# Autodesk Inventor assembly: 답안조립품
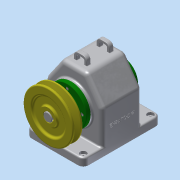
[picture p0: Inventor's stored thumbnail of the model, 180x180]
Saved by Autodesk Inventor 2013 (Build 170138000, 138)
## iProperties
Created: 2016-12
Part Number: 답안조립품
Document SubType Name: Assembly
Designer: Administrator
Author: Administrator
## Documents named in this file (15)
- C:\Users\Administrator\Desktop\461208V1012\답안조립품.iam
- C:\Users\Administrator\Desktop\461208V1012\1.본체.ipt
- C:\Users\Administrator\Desktop\461208V1012\뒤커버.ipt
- C:\Users\Administrator\Desktop\461208V1012\축.ipt
- C:\Users\Administrator\Desktop\461208V1012\베어링 6203.ipt
- C:\Users\Administrator\Desktop\461208V1012\키 - 6 x 6 x 22.ipt
- C:\Users\Administrator\Desktop\461208V1012\스퍼기어.ipt
- C:\Users\Administrator\Desktop\461208V1012\부시.ipt
- C:\Users\Administrator\Desktop\461208V1012\앞커버.ipt
- C:\Users\Administrator\Desktop\461208V1012\오일씰 28 40 8.ipt
- C:\Users\Administrator\Desktop\461208V1012\볼트 M3 x 10.ipt
- C:\Users\Administrator\Desktop\461208V1012\볼트 M3 x 8.ipt
- C:\Users\Administrator\Desktop\461208V1012\키 - 5 x 5 x 18.ipt
- C:\Users\Administrator\Desktop\461208V1012\V-벨트풀리.ipt
- C:\Users\Administrator\Desktop\461208V1012\멈춤나사 - M4x10.ipt
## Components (10 placed, 4 different names)
1. 1.본체:1
2. ISO 4762 M3 x 10:1
3. ISO 4762 M3 x 10:2
4. ISO 4762 M3 x 10:3
5. ISO 4762 M3 x 10:4
6. ISO 4762 M3 x 8:1
7. ISO 4762 M3 x 8:2
8. ISO 4762 M3 x 8:3
9. ISO 4762 M3 x 8:4
10. V-벨트풀리:1 — 각도:4, 플러쉬:1
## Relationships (2: Angle 1, Flush 1)
- 각도:4 [Angle]: V-벨트풀리:1
- 플러쉬:1 [Flush]: V-벨트풀리:1
